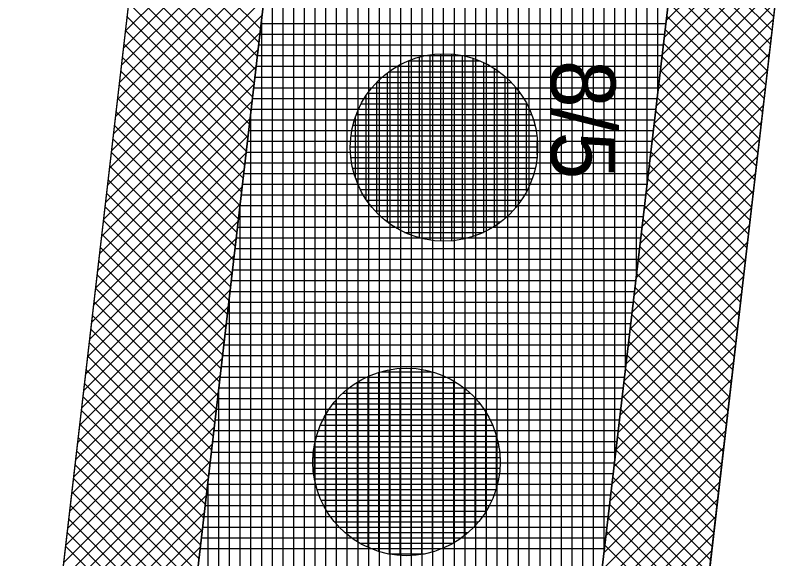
# Model space of a CAD drawing. Extents: x -565346 to -564154, y -1097386 to -1095620.
# Drawn here: x -564265.39 to -564250.97, y -1096573.78 to -1096563.64 of the extents above; entities that cross this region are included whole.
import ezdxf

# ---------------------------------------------------------------- set-up
doc = ezdxf.new("R2010")
doc.units = 0
for name, color, linetype in [('Vrstva 1', 7, 'Continuous'), ('Vrstva 13', 7, 'Continuous'), ('Vrstva 40', 7, 'Continuous'), ('Vrstva 41', 7, 'Continuous'), ('Vrstva 42', 7, 'Continuous'), ('Vrstva 43', 7, 'Continuous'), ('Vrstva 44', 7, 'Continuous')]:
    doc.layers.add(name, color=color, linetype=linetype)

msp = doc.modelspace()

# ---------------------------------------------------------------- linework, layer by layer
at = {"layer": 'Vrstva 1'}
msp.add_line((-564264.72, -1096575.85), (-564259.14, -1096527.84), dxfattribs=at)
at = {"layer": 'Vrstva 13'}
msp.add_line((-564247.38, -1096530.59), (-564252.76, -1096576.88), dxfattribs=at)
at = {"layer": 'Vrstva 41'}
for points in [[(-564230.6, -1096442.93), (-564234.67, -1096447.65), (-564259.14, -1096527.84), (-564264.72, -1096575.85), (-564272.07, -1096706.16), (-564269.623, -1096706.334), (-564262.228, -1096576.061), (-564256.683, -1096528.354)], [(-564221.399, -1096446.296), (-564223.301, -1096445.676), (-564228.215, -1096460.758), (-564240.675, -1096505.018), (-564249.271, -1096529.938), (-564254.757, -1096576.767), (-564262.137, -1096706.758), (-564260.141, -1096706.872), (-564252.76, -1096576.88), (-564247.38, -1096530.59), (-564238.75, -1096505.56), (-564226.29, -1096461.3)]]:
    msp.add_lwpolyline(points, close=True, dxfattribs=at)
at = {"layer": 'Vrstva 42'}
for p, q in [((-564260.487, -1096561.081), (-564263.334, -1096563.929)), ((-564260.524, -1096561.401), (-564263.372, -1096564.249)), ((-564250.969, -1096561.472), (-564253.23, -1096563.733)), ((-564263.068, -1096561.638), (-564260.814, -1096563.893)), ((-564260.561, -1096561.721), (-564263.409, -1096564.569)), ((-564251.006, -1096561.792), (-564253.268, -1096564.053)), ((-564263.098, -1096561.892), (-564260.843, -1096564.146)), ((-564253.013, -1096561.88), (-564251.224, -1096563.668)), ((-564260.599, -1096562.041), (-564263.446, -1096564.889)), ((-564263.127, -1096562.145), (-564260.873, -1096564.4)), ((-564251.044, -1096562.112), (-564253.305, -1096564.373)), ((-564253.043, -1096562.133), (-564251.254, -1096563.922)), ((-564260.636, -1096562.362), (-564263.483, -1096565.209)), ((-564253.072, -1096562.386), (-564251.283, -1096564.175)), ((-564263.157, -1096562.398), (-564260.902, -1096564.653)), ((-564251.081, -1096562.432), (-564253.343, -1096564.694)), ((-564263.186, -1096562.652), (-564260.931, -1096564.906)), ((-564253.102, -1096562.639), (-564251.313, -1096564.428)), ((-564260.673, -1096562.682), (-564263.52, -1096565.529)), ((-564251.118, -1096562.752), (-564253.38, -1096565.014)), ((-564263.215, -1096562.905), (-564260.961, -1096565.16)), ((-564253.132, -1096562.892), (-564251.342, -1096564.682)), ((-564260.71, -1096563.002), (-564263.558, -1096565.849)), ((-564251.155, -1096563.072), (-564253.418, -1096565.334)), ((-564263.245, -1096563.159), (-564260.99, -1096565.413)), ((-564253.161, -1096563.146), (-564251.372, -1096564.935)), ((-564260.747, -1096563.322), (-564263.595, -1096566.169)), ((-564251.192, -1096563.392), (-564253.455, -1096565.655)), ((-564253.191, -1096563.399), (-564251.401, -1096565.189)), ((-564263.274, -1096563.412), (-564261.02, -1096565.667)), ((-564260.784, -1096563.642), (-564263.632, -1096566.489)), ((-564263.304, -1096563.665), (-564261.049, -1096565.92)), ((-564253.221, -1096563.652), (-564251.431, -1096565.442)), ((-564251.23, -1096563.712), (-564253.493, -1096565.975)), ((-564260.822, -1096563.962), (-564263.669, -1096566.809)), ((-564263.333, -1096563.919), (-564261.079, -1096566.173)), ((-564253.25, -1096563.905), (-564251.46, -1096565.695)), ((-564251.267, -1096564.032), (-564253.53, -1096566.296)), ((-564263.363, -1096564.172), (-564261.108, -1096566.427)), ((-564253.28, -1096564.158), (-564251.49, -1096565.949)), ((-564260.859, -1096564.282), (-564263.706, -1096567.129)), ((-564251.304, -1096564.352), (-564253.568, -1096566.616)), ((-564253.31, -1096564.412), (-564251.519, -1096566.202)), ((-564263.392, -1096564.426), (-564261.138, -1096566.68)), ((-564260.896, -1096564.602), (-564263.744, -1096567.449)), ((-564263.422, -1096564.679), (-564261.167, -1096566.934)), ((-564251.341, -1096564.672), (-564253.605, -1096566.936)), ((-564253.339, -1096564.665), (-564251.548, -1096566.456)), ((-564260.933, -1096564.922), (-564263.781, -1096567.769)), ((-564263.451, -1096564.932), (-564261.197, -1096567.187)), ((-564253.369, -1096564.918), (-564251.578, -1096566.709)), ((-564251.378, -1096564.992), (-564253.643, -1096567.257)), ((-564260.97, -1096565.242), (-564263.818, -1096568.089)), ((-564263.481, -1096565.186), (-564261.226, -1096567.44)), ((-564253.399, -1096565.171), (-564251.607, -1096566.962)), ((-564251.416, -1096565.312), (-564253.68, -1096567.577)), ((-564261.008, -1096565.562), (-564263.855, -1096568.409)), ((-564263.51, -1096565.439), (-564261.255, -1096567.694)), ((-564253.428, -1096565.424), (-564251.637, -1096567.216)), ((-564263.539, -1096565.693), (-564261.285, -1096567.947)), ((-564251.453, -1096565.632), (-564253.718, -1096567.897)), ((-564253.458, -1096565.677), (-564251.666, -1096567.469)), ((-564261.045, -1096565.882), (-564263.892, -1096568.729)), ((-564263.569, -1096565.946), (-564261.314, -1096568.2)), ((-564251.49, -1096565.952), (-564253.755, -1096568.218)), ((-564253.488, -1096565.931), (-564251.696, -1096567.723)), ((-564261.082, -1096566.202), (-564263.93, -1096569.05)), ((-564263.598, -1096566.199), (-564261.344, -1096568.454)), ((-564251.527, -1096566.272), (-564253.793, -1096568.538)), ((-564253.517, -1096566.184), (-564251.725, -1096567.976)), ((-564261.119, -1096566.522), (-564263.967, -1096569.37)), ((-564263.628, -1096566.453), (-564261.373, -1096568.707)), ((-564253.547, -1096566.437), (-564251.755, -1096568.229)), ((-564263.657, -1096566.706), (-564261.403, -1096568.961)), ((-564251.564, -1096566.592), (-564253.831, -1096568.859)), ((-564253.577, -1096566.69), (-564251.784, -1096568.483)), ((-564261.156, -1096566.842), (-564264.004, -1096569.69)), ((-564263.687, -1096566.96), (-564261.432, -1096569.214)), ((-564251.602, -1096566.912), (-564253.868, -1096569.179)), ((-564253.606, -1096566.943), (-564251.813, -1096568.736)), ((-564261.194, -1096567.162), (-564264.041, -1096570.01)), ((-564263.716, -1096567.213), (-564261.462, -1096569.467)), ((-564251.639, -1096567.232), (-564253.906, -1096569.499)), ((-564253.636, -1096567.197), (-564251.843, -1096568.989)), ((-564261.231, -1096567.482), (-564264.078, -1096570.33)), ((-564263.746, -1096567.466), (-564261.491, -1096569.721)), ((-564251.676, -1096567.552), (-564253.943, -1096569.82)), ((-564253.665, -1096567.45), (-564251.872, -1096569.243)), ((-564263.775, -1096567.72), (-564261.521, -1096569.974)), ((-564253.695, -1096567.703), (-564251.902, -1096569.496)), ((-564261.268, -1096567.802), (-564264.116, -1096570.65)), ((-564251.713, -1096567.873), (-564253.981, -1096570.14)), ((-564263.804, -1096567.973), (-564261.55, -1096570.228)), ((-564253.725, -1096567.956), (-564251.931, -1096569.75)), ((-564261.305, -1096568.122), (-564264.153, -1096570.97)), ((-564263.834, -1096568.226), (-564261.579, -1096570.481)), ((-564251.75, -1096568.193), (-564254.018, -1096570.46)), ((-564253.754, -1096568.209), (-564251.961, -1096570.003)), ((-564261.342, -1096568.442), (-564264.19, -1096571.29)), ((-564263.863, -1096568.48), (-564261.609, -1096570.734)), ((-564251.788, -1096568.513), (-564254.056, -1096570.781)), ((-564253.784, -1096568.462), (-564251.99, -1096570.256)), ((-564263.893, -1096568.733), (-564261.638, -1096570.988)), ((-564253.814, -1096568.716), (-564252.02, -1096570.51)), ((-564261.38, -1096568.762), (-564264.227, -1096571.61)), ((-564251.825, -1096568.833), (-564254.093, -1096571.101)), ((-564263.922, -1096568.987), (-564261.668, -1096571.241)), ((-564253.843, -1096568.969), (-564252.049, -1096570.763)), ((-564261.417, -1096569.082), (-564264.264, -1096571.93)), ((-564251.862, -1096569.153), (-564254.131, -1096571.422)), ((-564263.952, -1096569.24), (-564261.697, -1096571.495)), ((-564253.873, -1096569.222), (-564252.079, -1096571.017)), ((-564261.454, -1096569.402), (-564264.302, -1096572.25)), ((-564263.981, -1096569.493), (-564261.727, -1096571.748)), ((-564251.899, -1096569.473), (-564254.168, -1096571.742)), ((-564253.903, -1096569.475), (-564252.108, -1096571.27)), ((-564261.491, -1096569.722), (-564264.339, -1096572.57)), ((-564264.011, -1096569.747), (-564261.756, -1096572.001)), ((-564253.932, -1096569.728), (-564252.137, -1096571.523)), ((-564251.936, -1096569.793), (-564254.206, -1096572.062)), ((-564264.04, -1096570), (-564261.786, -1096572.255)), ((-564253.962, -1096569.982), (-564252.167, -1096571.777)), ((-564261.528, -1096570.042), (-564264.376, -1096572.89)), ((-564251.973, -1096570.113), (-564254.243, -1096572.383)), ((-564264.07, -1096570.254), (-564261.815, -1096572.508)), ((-564253.992, -1096570.235), (-564252.196, -1096572.03)), ((-564261.566, -1096570.363), (-564264.413, -1096573.21)), ((-564252.011, -1096570.433), (-564254.281, -1096572.703)), ((-564264.099, -1096570.507), (-564261.844, -1096572.762)), ((-564254.021, -1096570.488), (-564252.226, -1096572.284)), ((-564261.603, -1096570.683), (-564264.45, -1096573.53)), ((-564252.048, -1096570.753), (-564254.318, -1096573.023)), ((-564254.051, -1096570.741), (-564252.255, -1096572.537)), ((-564264.128, -1096570.76), (-564261.874, -1096573.015)), ((-564261.64, -1096571.003), (-564264.488, -1096573.85)), ((-564264.158, -1096571.014), (-564261.903, -1096573.268)), ((-564254.081, -1096570.994), (-564252.285, -1096572.79)), ((-564252.085, -1096571.073), (-564254.356, -1096573.344)), ((-564261.677, -1096571.323), (-564264.525, -1096574.17)), ((-564264.187, -1096571.267), (-564261.933, -1096573.522)), ((-564254.11, -1096571.247), (-564252.314, -1096573.044)), ((-564252.122, -1096571.393), (-564254.394, -1096573.664)), ((-564264.217, -1096571.521), (-564261.962, -1096573.775)), ((-564254.14, -1096571.501), (-564252.344, -1096573.297)), ((-564261.714, -1096571.643), (-564264.562, -1096574.49)), ((-564252.159, -1096571.713), (-564254.431, -1096573.985)), ((-564254.17, -1096571.754), (-564252.373, -1096573.551)), ((-564264.246, -1096571.774), (-564261.992, -1096574.028)), ((-564261.752, -1096571.963), (-564264.599, -1096574.81)), ((-564264.276, -1096572.027), (-564262.021, -1096574.282)), ((-564252.197, -1096572.033), (-564254.469, -1096574.305)), ((-564254.199, -1096572.007), (-564252.402, -1096573.804)), ((-564261.789, -1096572.283), (-564264.636, -1096575.13)), ((-564264.305, -1096572.281), (-564262.051, -1096574.535)), ((-564254.229, -1096572.26), (-564252.432, -1096574.057)), ((-564252.234, -1096572.353), (-564254.506, -1096574.625)), ((-564261.826, -1096572.603), (-564264.674, -1096575.45)), ((-564264.335, -1096572.534), (-564262.08, -1096574.789)), ((-564254.259, -1096572.513), (-564252.461, -1096574.311)), ((-564252.271, -1096572.673), (-564254.544, -1096574.946)), ((-564254.288, -1096572.767), (-564252.491, -1096574.564)), ((-564261.863, -1096572.923), (-564264.711, -1096575.77)), ((-564264.364, -1096572.788), (-564262.11, -1096575.042)), ((-564264.394, -1096573.041), (-564262.139, -1096575.295)), ((-564252.308, -1096572.993), (-564254.581, -1096575.266)), ((-564254.318, -1096573.02), (-564252.52, -1096574.817)), ((-564261.9, -1096573.243), (-564264.733, -1096576.075)), ((-564264.423, -1096573.294), (-564262.168, -1096575.549)), ((-564252.345, -1096573.313), (-564254.619, -1096575.586)), ((-564254.348, -1096573.273), (-564252.55, -1096575.071)), ((-564261.938, -1096573.563), (-564264.75, -1096576.375)), ((-564264.452, -1096573.548), (-564262.198, -1096575.802)), ((-564252.383, -1096573.633), (-564254.656, -1096575.907)), ((-564254.377, -1096573.526), (-564252.579, -1096575.324))]:
    msp.add_line(p, q, dxfattribs=at)
at = {"layer": 'Vrstva 43'}
for p, q in [((-564253.39, -1096565.098), (-564253.39, -1096517.569)), ((-564253.59, -1096566.805), (-564253.59, -1096518.224)), ((-564253.79, -1096568.513), (-564253.79, -1096518.879)), ((-564253.99, -1096570.22), (-564253.99, -1096519.534)), ((-564254.19, -1096571.927), (-564254.19, -1096520.189)), ((-564254.39, -1096573.634), (-564254.39, -1096520.844)), ((-564254.59, -1096575.341), (-564254.59, -1096521.499)), ((-564254.79, -1096577.348), (-564254.79, -1096522.154)), ((-564254.99, -1096580.871), (-564254.99, -1096522.809)), ((-564255.19, -1096584.394), (-564255.19, -1096523.464)), ((-564255.39, -1096587.917), (-564255.39, -1096524.119)), ((-564255.59, -1096591.439), (-564255.59, -1096524.774)), ((-564255.79, -1096594.962), (-564255.79, -1096525.429)), ((-564255.99, -1096598.485), (-564255.99, -1096526.084)), ((-564256.19, -1096602.008), (-564256.19, -1096526.739)), ((-564256.39, -1096605.531), (-564256.39, -1096527.394)), ((-564256.59, -1096609.053), (-564256.59, -1096528.049)), ((-564256.79, -1096612.576), (-564256.79, -1096529.275)), ((-564256.99, -1096616.099), (-564256.99, -1096530.995)), ((-564257.19, -1096619.622), (-564257.19, -1096532.716)), ((-564257.39, -1096623.145), (-564257.39, -1096534.437)), ((-564257.59, -1096626.667), (-564257.59, -1096536.157)), ((-564257.79, -1096630.19), (-564257.79, -1096537.878)), ((-564257.99, -1096633.713), (-564257.99, -1096539.599)), ((-564258.19, -1096637.236), (-564258.19, -1096541.32)), ((-564258.39, -1096640.759), (-564258.39, -1096543.04)), ((-564258.59, -1096644.281), (-564258.59, -1096544.761)), ((-564258.79, -1096647.804), (-564258.79, -1096546.482)), ((-564258.99, -1096651.327), (-564258.99, -1096548.203)), ((-564259.19, -1096654.85), (-564259.19, -1096549.923)), ((-564259.39, -1096658.372), (-564259.39, -1096551.644)), ((-564259.59, -1096661.895), (-564259.59, -1096553.365)), ((-564259.79, -1096665.418), (-564259.79, -1096555.085)), ((-564259.99, -1096668.941), (-564259.99, -1096556.806)), ((-564260.19, -1096672.464), (-564260.19, -1096558.527)), ((-564260.39, -1096675.986), (-564260.39, -1096560.248)), ((-564260.59, -1096679.509), (-564260.59, -1096561.968)), ((-564260.79, -1096683.032), (-564260.79, -1096563.689)), ((-564260.802, -1096563.79), (-564253.237, -1096563.79)), ((-564260.825, -1096563.99), (-564253.26, -1096563.99)), ((-564260.848, -1096564.19), (-564253.284, -1096564.19)), ((-564260.871, -1096564.39), (-564253.307, -1096564.39)), ((-564260.895, -1096564.59), (-564253.33, -1096564.59)), ((-564260.918, -1096564.79), (-564253.354, -1096564.79)), ((-564260.941, -1096564.99), (-564253.377, -1096564.99)), ((-564260.964, -1096565.19), (-564253.401, -1096565.19)), ((-564260.99, -1096686.555), (-564260.99, -1096565.41)), ((-564260.988, -1096565.39), (-564253.424, -1096565.39)), ((-564261.011, -1096565.59), (-564253.448, -1096565.59)), ((-564261.034, -1096565.79), (-564253.471, -1096565.79)), ((-564261.057, -1096565.99), (-564253.494, -1096565.99)), ((-564261.081, -1096566.19), (-564253.518, -1096566.19)), ((-564261.104, -1096566.39), (-564253.541, -1096566.39)), ((-564261.127, -1096566.59), (-564253.565, -1096566.59)), ((-564261.15, -1096566.79), (-564253.588, -1096566.79)), ((-564261.174, -1096566.99), (-564253.612, -1096566.99)), ((-564261.19, -1096690.078), (-564261.19, -1096567.13)), ((-564261.197, -1096567.19), (-564253.635, -1096567.19)), ((-564261.22, -1096567.39), (-564253.658, -1096567.39)), ((-564261.243, -1096567.59), (-564253.682, -1096567.59)), ((-564261.267, -1096567.79), (-564253.705, -1096567.79)), ((-564261.29, -1096567.99), (-564253.729, -1096567.99)), ((-564261.313, -1096568.19), (-564253.752, -1096568.19)), ((-564261.336, -1096568.39), (-564253.776, -1096568.39)), ((-564261.36, -1096568.59), (-564253.799, -1096568.59)), ((-564261.39, -1096693.6), (-564261.39, -1096568.851)), ((-564261.383, -1096568.79), (-564253.822, -1096568.79)), ((-564261.406, -1096568.99), (-564253.846, -1096568.99)), ((-564261.429, -1096569.19), (-564253.869, -1096569.19)), ((-564261.453, -1096569.39), (-564253.893, -1096569.39)), ((-564261.476, -1096569.59), (-564253.916, -1096569.59)), ((-564261.499, -1096569.79), (-564253.94, -1096569.79)), ((-564261.522, -1096569.99), (-564253.963, -1096569.99)), ((-564261.546, -1096570.19), (-564253.987, -1096570.19)), ((-564261.569, -1096570.39), (-564254.01, -1096570.39)), ((-564261.592, -1096570.59), (-564254.033, -1096570.59)), ((-564261.59, -1096697.123), (-564261.59, -1096570.572)), ((-564261.615, -1096570.79), (-564254.057, -1096570.79)), ((-564261.639, -1096570.99), (-564254.08, -1096570.99)), ((-564261.662, -1096571.19), (-564254.104, -1096571.19)), ((-564261.685, -1096571.39), (-564254.127, -1096571.39)), ((-564261.708, -1096571.59), (-564254.151, -1096571.59)), ((-564261.732, -1096571.79), (-564254.174, -1096571.79)), ((-564261.755, -1096571.99), (-564254.197, -1096571.99)), ((-564261.778, -1096572.19), (-564254.221, -1096572.19)), ((-564261.79, -1096700.646), (-564261.79, -1096572.293)), ((-564261.801, -1096572.39), (-564254.244, -1096572.39)), ((-564261.825, -1096572.59), (-564254.268, -1096572.59)), ((-564261.848, -1096572.79), (-564254.291, -1096572.79)), ((-564261.871, -1096572.99), (-564254.315, -1096572.99)), ((-564261.894, -1096573.19), (-564254.338, -1096573.19)), ((-564261.918, -1096573.39), (-564254.361, -1096573.39)), ((-564261.941, -1096573.59), (-564254.385, -1096573.59))]:
    msp.add_line(p, q, dxfattribs=at)
msp.add_lwpolyline([(-564261.274, -1096726.84), (-564260.141, -1096706.872), (-564262.137, -1096706.758), (-564254.757, -1096576.767), (-564249.271, -1096529.938), (-564240.675, -1096505.018), (-564228.215, -1096460.758), (-564223.301, -1096445.676), (-564221.399, -1096446.296), (-564218.92, -1096438.69), (-564229.82, -1096442.05), (-564230.6, -1096442.93), (-564256.683, -1096528.354), (-564262.228, -1096576.061), (-564269.623, -1096706.334), (-564272.07, -1096706.16), (-564273.28, -1096725.96)], dxfattribs=at)
at = {"layer": 'Vrstva 44'}
for p, q in [((-564257.64, -1096567.834), (-564257.64, -1096564.375)), ((-564257.44, -1096567.853), (-564257.44, -1096564.357)), ((-564257.24, -1096567.847), (-564257.24, -1096564.362)), ((-564257.04, -1096567.818), (-564257.04, -1096564.389)), ((-564258.056, -1096564.49), (-564256.708, -1096564.49)), ((-564258.04, -1096567.726), (-564258.04, -1096564.483)), ((-564257.84, -1096567.793), (-564257.84, -1096564.415)), ((-564256.84, -1096567.765), (-564256.84, -1096564.442)), ((-564256.64, -1096567.687), (-564256.64, -1096564.522)), ((-564258.413, -1096564.69), (-564256.356, -1096564.69)), ((-564258.24, -1096567.628), (-564258.24, -1096564.58)), ((-564256.44, -1096567.576), (-564256.44, -1096564.632)), ((-564258.44, -1096567.498), (-564258.44, -1096564.709)), ((-564256.24, -1096567.426), (-564256.24, -1096564.782)), ((-564258.642, -1096564.89), (-564256.126, -1096564.89)), ((-564258.64, -1096567.32), (-564258.64, -1096564.888)), ((-564256.04, -1096567.221), (-564256.04, -1096564.984)), ((-564258.81, -1096565.09), (-564255.959, -1096565.09)), ((-564258.84, -1096567.072), (-564258.84, -1096565.136)), ((-564258.931, -1096565.29), (-564255.837, -1096565.29)), ((-564255.84, -1096566.923), (-564255.84, -1096565.283)), ((-564259.04, -1096566.67), (-564259.04, -1096565.541)), ((-564259.022, -1096565.49), (-564255.748, -1096565.49)), ((-564259.084, -1096565.69), (-564255.685, -1096565.69)), ((-564259.119, -1096565.89), (-564255.647, -1096565.89)), ((-564255.64, -1096566.239), (-564255.64, -1096565.988)), ((-564259.132, -1096566.09), (-564255.635, -1096566.09)), ((-564259.123, -1096566.29), (-564255.646, -1096566.29)), ((-564259.09, -1096566.49), (-564255.679, -1096566.49)), ((-564259.032, -1096566.69), (-564255.736, -1096566.69)), ((-564258.946, -1096566.89), (-564255.822, -1096566.89)), ((-564258.829, -1096567.09), (-564255.941, -1096567.09)), ((-564258.668, -1096567.29), (-564256.098, -1096567.29)), ((-564258.451, -1096567.49), (-564256.317, -1096567.49)), ((-564258.119, -1096567.69), (-564256.647, -1096567.69)), ((-564258.6, -1096573.645), (-564258.6, -1096570.303)), ((-564258.56, -1096570.29), (-564257.614, -1096570.29)), ((-564258.4, -1096573.693), (-564258.4, -1096570.253)), ((-564258.2, -1096573.718), (-564258.2, -1096570.229)), ((-564258, -1096573.721), (-564258, -1096570.228)), ((-564257.8, -1096573.701), (-564257.8, -1096570.249)), ((-564257.6, -1096573.654), (-564257.6, -1096570.294)), ((-564258.8, -1096573.569), (-564258.8, -1096570.379)), ((-564257.4, -1096573.583), (-564257.4, -1096570.364)), ((-564257.2, -1096573.483), (-564257.2, -1096570.466)), ((-564259.011, -1096570.49), (-564257.16, -1096570.49)), ((-564259, -1096573.464), (-564259, -1096570.484)), ((-564257, -1096573.346), (-564257, -1096570.602)), ((-564259.273, -1096570.69), (-564256.898, -1096570.69)), ((-564259.2, -1096573.32), (-564259.2, -1096570.628)), ((-564259.456, -1096570.89), (-564256.712, -1096570.89)), ((-564259.4, -1096573.127), (-564259.4, -1096570.821)), ((-564256.8, -1096573.162), (-564256.8, -1096570.788)), ((-564259.6, -1096572.848), (-564259.6, -1096571.101)), ((-564259.594, -1096571.09), (-564256.576, -1096571.09)), ((-564256.6, -1096572.9), (-564256.6, -1096571.051)), ((-564259.693, -1096571.29), (-564256.474, -1096571.29)), ((-564259.764, -1096571.49), (-564256.404, -1096571.49)), ((-564256.4, -1096572.446), (-564256.4, -1096571.506)), ((-564259.81, -1096571.69), (-564256.359, -1096571.69)), ((-564259.8, -1096572.308), (-564259.8, -1096571.64)), ((-564259.832, -1096571.89), (-564256.338, -1096571.89)), ((-564259.829, -1096572.09), (-564256.338, -1096572.09)), ((-564259.803, -1096572.29), (-564256.364, -1096572.29)), ((-564259.755, -1096572.49), (-564256.414, -1096572.49)), ((-564259.681, -1096572.69), (-564256.489, -1096572.69)), ((-564259.573, -1096572.89), (-564256.593, -1096572.89)), ((-564259.431, -1096573.09), (-564256.739, -1096573.09)), ((-564259.235, -1096573.29), (-564256.932, -1096573.29)), ((-564258.954, -1096573.49), (-564257.213, -1096573.49)), ((-564258.419, -1096573.69), (-564257.75, -1096573.69))]:
    msp.add_line(p, q, dxfattribs=at)
for centre in [(-564257.384, -1096566.104), (-564258.084, -1096571.974)]:
    msp.add_circle(centre, 1.75, dxfattribs=at)

# ---------------------------------------------------------------- texts
at = {"layer": 'Vrstva 40'}
msp.add_text('8/5', height=1.2, rotation=270, dxfattribs=at).set_placement((-564255.38, -1096564.47))

doc.saveas('drawing.dxf')
